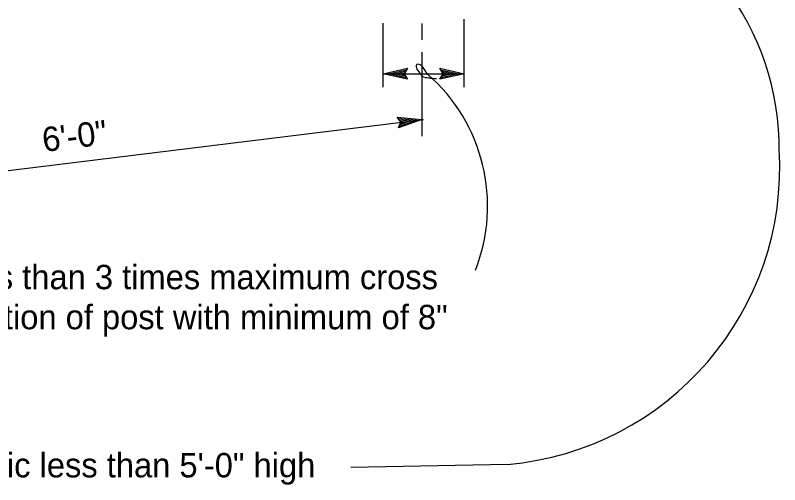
# Model space of a CAD drawing. Extents: x 6710407 to 6714861, y 1868090 to 1871317.
# Drawn here: x 6711941.5 to 6712129.2, y 1870227.4 to 1870342.8 of the extents above; entities that cross this region are included whole.
import ezdxf

# ---------------------------------------------------------------- set-up
doc = ezdxf.new("R2010")
doc.units = 0
for name, color, linetype in [('G-MARK', 7, 'Continuous'), ('G-TEXT', 7, 'Continuous'), ('Nongeo Data(60)', 7, 'Continuous')]:
    doc.layers.add(name, color=color, linetype=linetype)

msp = doc.modelspace()

# ---------------------------------------------------------------- linework, layer by layer
at = {"layer": 'G-MARK'}
for p, q in [((6712051.69, 1870325.14), (6712051.7, 1870341.89)), ((6712031.77, 1870325.14), (6712031.78, 1870340.89)), ((6712031.78, 1870328.47), (6712051.7, 1870328.47)), ((6711873.35, 1870296.51), (6712041.75, 1870317.18)), ((6712062.36, 1870232.39), (6712023.87, 1870231.64))]:
    msp.add_line(p, q, dxfattribs=at)
for points in [[(6712041.34, 1870340.81), (6712041.34, 1870336.81)], [(6712041.34, 1870333.81), (6712041.34, 1870313.12)]]:
    msp.add_lwpolyline(points, dxfattribs=at)
for centre, radius, start, end in [((6712063.9, 1870310.34), 65.14, 358.9398, 76.5372), ((6712014.3, 1870295.9), 43.15, 338.5796, 48.8649), ((6712055.92, 1870305.38), 73.27, 275.043, 3.6311)]:
    msp.add_arc(centre, radius, start, end, dxfattribs=at)
msp.add_spline([(6712042.69, 1870328.4), (6712042.12, 1870329.25), (6712041.4, 1870330.24), (6712040.68, 1870330.77), (6712040.06, 1870330.77), (6712039.97, 1870329.97), (6712040.77, 1870328.62), (6712041.4, 1870327.91), (6712042.92, 1870327.46), (6712044, 1870327.37), (6712044.8, 1870327.28), (6712044.89, 1870327.28)], degree=3, dxfattribs=at)
at = {"layer": 'G-TEXT'}
for p, q in [((6712031.78, 1870328.47), (6712037.78, 1870329.8)), ((6712037.78, 1870327.13), (6712031.78, 1870328.47)), ((6712031.78, 1870328.47), (6712031.78, 1870328.47)), ((6712037.57, 1870327.49), (6712033.16, 1870328.47)), ((6712033.17, 1870328.47), (6712037.55, 1870329.44)), ((6712034.55, 1870328.47), (6712037.37, 1870329.09)), ((6712037.33, 1870327.85), (6712034.55, 1870328.47)), ((6712035.93, 1870328.47), (6712037.14, 1870328.73)), ((6712037.16, 1870328.19), (6712035.93, 1870328.47)), ((6712037.78, 1870329.8), (6712036.98, 1870328.47)), ((6712036.98, 1870328.47), (6712037.78, 1870327.13)), ((6712037.78, 1870329.8), (6712037.78, 1870329.8)), ((6712046.5, 1870328.47), (6712045.7, 1870329.81)), ((6712045.7, 1870329.81), (6712045.7, 1870329.81)), ((6712045.7, 1870329.81), (6712051.7, 1870328.47)), ((6712051.7, 1870328.47), (6712045.7, 1870327.14)), ((6712045.7, 1870327.14), (6712046.5, 1870328.47)), ((6712045.92, 1870329.45), (6712050.32, 1870328.47)), ((6712050.31, 1870328.47), (6712045.94, 1870327.5)), ((6712048.94, 1870328.47), (6712046.12, 1870327.85)), ((6712046.16, 1870329.09), (6712048.94, 1870328.47)), ((6712046.33, 1870328.75), (6712047.56, 1870328.47)), ((6712047.56, 1870328.47), (6712046.35, 1870328.21)), ((6712051.7, 1870328.47), (6712051.7, 1870328.47)), ((6712037.78, 1870327.13), (6712037.78, 1870327.13)), ((6712045.7, 1870327.14), (6712045.7, 1870327.14)), ((6712036.18, 1870316.55), (6712035.22, 1870317.78)), ((6712035.22, 1870317.78), (6712035.22, 1870317.78)), ((6712035.22, 1870317.78), (6712041.34, 1870317.18)), ((6712035.48, 1870317.46), (6712039.97, 1870317.02)), ((6712041.34, 1870317.18), (6712035.54, 1870315.13)), ((6712035.75, 1870317.13), (6712038.59, 1870316.85)), ((6712041.34, 1870317.18), (6712041.34, 1870317.18)), ((6712035.54, 1870315.13), (6712036.18, 1870316.55)), ((6712039.96, 1870317.01), (6712035.73, 1870315.52)), ((6712038.59, 1870316.85), (6712035.87, 1870315.88)), ((6712035.97, 1870316.81), (6712037.22, 1870316.68)), ((6712037.22, 1870316.68), (6712036.06, 1870316.27)), ((6712035.54, 1870315.13), (6712035.54, 1870315.13))]:
    msp.add_line(p, q, dxfattribs=at)

# ---------------------------------------------------------------- texts
at = {"layer": 'Nongeo Data(60)'}
msp.add_text('6\'-0"', height=6, rotation=7, dxfattribs=at).set_placement((6711948.44, 1870309.23))
for s, p in [('Not less than 3 times maximum cross', (6711911.95, 1870275.48)), ('section of post with minimum of 8"', (6711926.18, 1870265.64)), ('2\'-6" for fabric less than 5\'-0" high', (6711895.78, 1870229.21))]:
    msp.add_text(s, height=6, dxfattribs=at).set_placement(p)

doc.saveas('drawing.dxf')
